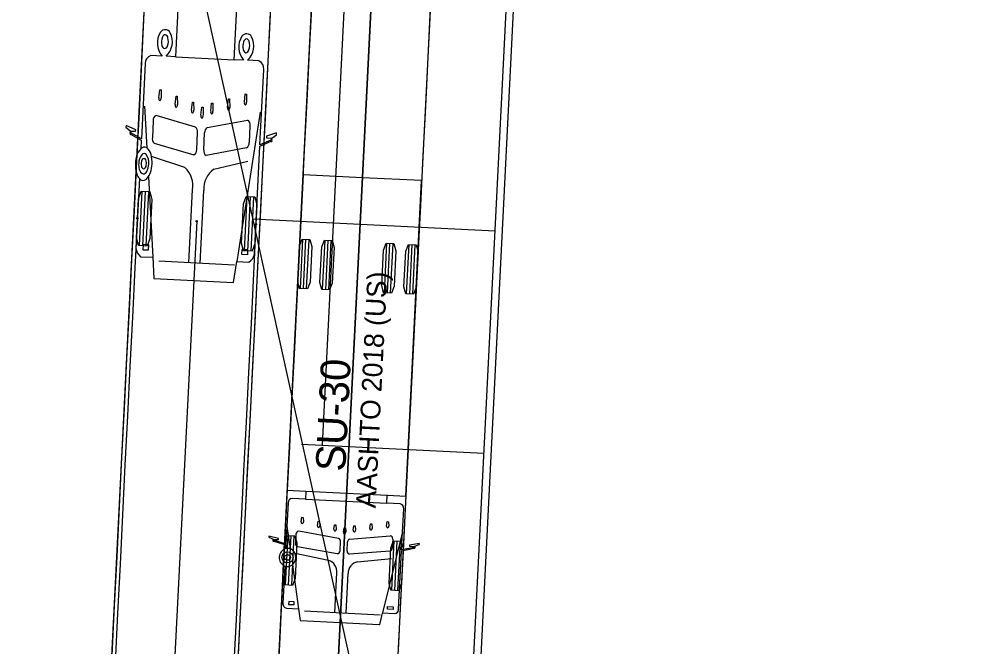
# Model space of a CAD drawing. Extents: x 260275 to 261282, y 610916 to 614143.
# Drawn here: x 261020 to 261084.3, y 612016.8 to 612059.1 of the extents above; entities that cross this region are included whole.
import ezdxf

# ---------------------------------------------------------------- set-up
doc = ezdxf.new("R2010")
doc.units = 0
for name, color, linetype in [('GE_X_Alignment', 7, 'Continuous'), ('PV_P_Curb', 7, 'Continuous'), ('PV_P_EOP', 7, 'Continuous'), ('PV_P_Joint', 7, 'Continuous'), ('UT_X_Water_Cells', 7, 'Continuous')]:
    doc.layers.add(name, color=color, linetype=linetype)

msp = doc.modelspace()

# ---------------------------------------------------------------- linework, layer by layer
at = {"layer": 'GE_X_Alignment'}
msp.add_line((260986.249, 610915.954), (261148.276, 614142.838), dxfattribs=at)
at = {"layer": 'PV_P_Curb'}
msp.add_line((261049.53, 611984.642), (261053.627, 612066.228), dxfattribs=at)
at = {"layer": 'PV_P_EOP'}
for p, q in [((261045.801, 612000.096), (261031.212, 612066.209)), ((261049.031, 611984.667), (261053.122, 612066.147))]:
    msp.add_line(p, q, dxfattribs=at)
at = {"layer": 'PV_P_Joint'}
for p, q in [((261040.428, 612030.404), (261042.684, 612075.347)), ((261035.717, 612045.659), (261052.052, 612044.839)), ((261039.021, 612030.475), (261051.3, 612029.858))]:
    msp.add_line(p, q, dxfattribs=at)
at = {"layer": 'UT_X_Water_Cells'}
for p, q in [((261044.031, 612066.726), (261023.69, 611661.632)), ((261029.631, 612056.616), (261028.857, 612056.655)), ((261030.518, 612056.572), (261034.487, 612056.372)), ((261036.148, 612056.289), (261035.373, 612056.328)), ((261029.404, 612053.801), (261029.468, 612054.348)), ((261029.468, 612054.348), (261029.55, 612054.344)), ((261029.55, 612054.344), (261029.559, 612053.793)), ((261030.501, 612053.36), (261030.564, 612053.907)), ((261030.564, 612053.907), (261030.647, 612053.903)), ((261030.647, 612053.903), (261030.655, 612053.352)), ((261034.027, 612053.158), (261034.091, 612053.73)), ((261034.091, 612053.73), (261034.173, 612053.726)), ((261034.173, 612053.726), (261034.181, 612053.15)), ((261035.162, 612053.512), (261035.226, 612054.059)), ((261035.226, 612054.059), (261035.308, 612054.055)), ((261035.308, 612054.055), (261035.317, 612053.504)), ((261028.435, 612053.233), (261028.587, 612050.433)), ((261031.6, 612052.97), (261031.663, 612053.517)), ((261031.663, 612053.517), (261031.746, 612053.513)), ((261031.746, 612053.513), (261031.754, 612052.962)), ((261032.232, 612052.629), (261032.295, 612053.176)), ((261032.295, 612053.176), (261032.378, 612053.172)), ((261032.378, 612053.172), (261032.386, 612052.622)), ((261032.895, 612052.905), (261032.958, 612053.452)), ((261032.958, 612053.452), (261033.041, 612053.448)), ((261033.041, 612053.448), (261033.049, 612052.897)), ((261031.879, 612051.833), (261029.221, 612052.612)), ((261032.657, 612051.794), (261035.38, 612052.303)), ((261036.225, 612052.842), (261034.653, 612042.773)), ((261029.021, 612052.251), (261028.964, 612051.122)), ((261035.543, 612051.924), (261035.487, 612050.794)), ((261027.489, 612051.551), (261027.47, 612051.569)), ((261027.515, 612051.551), (261027.489, 612051.551)), ((261031.955, 612050.326), (261032.012, 612051.455)), ((261032.43, 612050.302), (261032.487, 612051.432)), ((261036.971, 612051.076), (261036.997, 612051.074)), ((261036.997, 612051.074), (261037.018, 612051.089)), ((261029.097, 612050.744), (261031.755, 612049.966)), ((261035.317, 612050.432), (261032.593, 612049.923)), ((261031.149, 612049.103), (261028.908, 612049.852)), ((261033.11, 612049.004), (261035.403, 612049.523)), ((261028.694, 612048.471), (261028.99, 612043.058)), ((261028.09, 612048.368), (261027.854, 612043.673)), ((261028.092, 612043.844), (261028.276, 612047.506)), ((261028.321, 612043.832), (261028.505, 612047.494)), ((261028.55, 612043.821), (261028.734, 612047.483)), ((261031.428, 612042.71), (261031.673, 612047.595)), ((261032.192, 612042.671), (261032.438, 612047.557)), ((261035.167, 612043.489), (261035.351, 612047.151)), ((261035.396, 612043.477), (261035.58, 612047.139)), ((261035.625, 612043.466), (261035.809, 612047.128)), ((261031.95, 612045.486), (261010.925, 611626.741)), ((261038.94, 612040.955), (261039.108, 612044.284)), ((261039.148, 612040.945), (261039.316, 612044.274)), ((261039.357, 612040.934), (261039.524, 612044.264)), ((261040.439, 612040.88), (261040.606, 612044.209)), ((261040.647, 612040.87), (261040.814, 612044.199)), ((261040.855, 612040.859), (261041.022, 612044.188)), ((261044.6, 612040.671), (261044.767, 612044)), ((261044.808, 612040.661), (261044.975, 612043.99)), ((261045.016, 612040.65), (261045.183, 612043.979)), ((261028.343, 612043.927), (261028.325, 612043.571)), ((261028.325, 612043.571), (261028.704, 612043.552)), ((261028.721, 612043.908), (261028.343, 612043.927)), ((261028.704, 612043.552), (261028.721, 612043.908)), ((261034.987, 612043.237), (261035.005, 612043.592)), ((261035.005, 612043.592), (261035.383, 612043.573)), ((261035.383, 612043.573), (261035.366, 612043.218)), ((261046.098, 612040.596), (261046.265, 612043.925)), ((261046.306, 612040.585), (261046.473, 612043.915)), ((261046.514, 612040.575), (261046.681, 612043.904)), ((261029.394, 612042.812), (261034.492, 612042.556)), ((261035.366, 612043.218), (261034.987, 612043.237)), ((261029.068, 612041.626), (261034.432, 612041.356)), ((261039.302, 612027.3), (261044.787, 612027.025)), ((261039.275, 612026.769), (261044.76, 612026.494)), ((261038.984, 612025.242), (261039.035, 612025.54)), ((261039.035, 612025.54), (261039.118, 612025.536)), ((261039.118, 612025.536), (261039.138, 612025.234)), ((261038.028, 612024.954), (261038.245, 612023.42)), ((261040.09, 612024.976), (261040.14, 612025.274)), ((261040.14, 612025.274), (261040.223, 612025.269)), ((261040.223, 612025.269), (261040.244, 612024.968)), ((261041.196, 612024.738), (261041.247, 612025.035)), ((261041.247, 612025.035), (261041.33, 612025.031)), ((261041.33, 612025.031), (261041.35, 612024.73)), ((261041.835, 612024.537), (261041.886, 612024.835)), ((261041.886, 612024.835), (261041.969, 612024.831)), ((261041.969, 612024.831), (261041.989, 612024.529)), ((261042.491, 612024.673), (261042.542, 612024.97)), ((261042.542, 612024.97), (261042.624, 612024.966)), ((261042.624, 612024.966), (261042.645, 612024.665)), ((261043.616, 612024.785), (261043.667, 612025.096)), ((261043.667, 612025.096), (261043.749, 612025.092)), ((261043.749, 612025.092), (261043.77, 612024.777)), ((261044.742, 612024.953), (261044.793, 612025.251)), ((261044.793, 612025.251), (261044.876, 612025.246)), ((261044.876, 612025.246), (261044.897, 612024.945)), ((261037.937, 612020.98), (261038.105, 612024.31)), ((261038.146, 612020.97), (261038.313, 612024.299)), ((261038.354, 612020.96), (261038.521, 612024.289)), ((261038.636, 612024.404), (261038.605, 612023.788)), ((261041.501, 612024.11), (261038.828, 612024.596)), ((261042.279, 612024.071), (261044.988, 612024.287)), ((261045.819, 612024.562), (261044.478, 612019.095)), ((261045.159, 612024.076), (261045.128, 612023.46)), ((261038.747, 612023.578), (261041.42, 612023.092)), ((261041.612, 612023.285), (261041.642, 612023.901)), ((261042.086, 612023.261), (261042.117, 612023.877)), ((261045.095, 612020.621), (261045.262, 612023.95)), ((261045.303, 612020.611), (261045.47, 612023.94)), ((261045.511, 612020.6), (261045.678, 612023.929)), ((261040.834, 612022.634), (261038.579, 612023.095)), ((261044.966, 612023.266), (261042.258, 612023.05)), ((261042.795, 612022.536), (261045.073, 612022.767)), ((261037.893, 612022.254), (261037.766, 612019.735)), ((261038.396, 612022.345), (261038.815, 612019.379)), ((261041.258, 612019.134), (261041.392, 612021.798)), ((261042.023, 612019.095), (261042.156, 612021.76)), ((261038.149, 612019.869), (261038.139, 612019.675)), ((261038.139, 612019.675), (261038.518, 612019.656)), ((261038.527, 612019.85), (261038.149, 612019.869)), ((261038.518, 612019.656), (261038.527, 612019.85)), ((261044.801, 612019.341), (261044.811, 612019.535)), ((261044.811, 612019.535), (261045.189, 612019.516)), ((261039.224, 612019.236), (261044.322, 612018.98)), ((261045.18, 612019.322), (261044.801, 612019.341)), ((261045.189, 612019.516), (261045.18, 612019.322))]:
    msp.add_line(p, q, dxfattribs=at)
for points in [[(261009.34, 611680.102), (261030.965, 612110.617), (261039.455, 612110.191), (261039.447, 612110.045), (261039.447, 612110.045)], [(261039.447, 612110.045), (261018.12, 611685.301)], [(261020.965, 611687.133), (261041.34, 612092.893), (261049.33, 612092.492), (261049.322, 612092.345), (261049.322, 612092.345)], [(261049.322, 612092.345), (261028.546, 611678.469)], [(261041.039, 612086.901), (261040.872, 612083.572), (261040.705, 612080.244), (261040.537, 612076.915), (261040.37, 612073.586), (261040.203, 612070.258), (261040.036, 612066.929), (261039.869, 612063.601), (261039.702, 612060.272), (261039.535, 612056.943), (261039.367, 612053.615), (261039.2, 612050.286), (261039.033, 612046.958), (261038.866, 612043.629), (261038.699, 612040.3), (261038.532, 612036.972), (261038.365, 612033.643), (261038.198, 612030.314), (261038.03, 612026.986), (261037.863, 612023.657), (261037.696, 612020.329), (261037.529, 612017), (261037.362, 612013.671)], [(261049.029, 612086.5), (261048.862, 612083.171), (261048.694, 612079.843), (261048.527, 612076.514), (261048.36, 612073.185), (261048.193, 612069.857), (261048.026, 612066.528), (261047.859, 612063.199), (261047.692, 612059.871), (261047.525, 612056.542), (261047.357, 612053.214), (261047.19, 612049.885), (261047.023, 612046.556), (261046.856, 612043.228), (261046.689, 612039.899), (261046.522, 612036.57), (261046.355, 612033.242), (261046.187, 612029.913), (261046.02, 612026.585), (261045.853, 612023.256), (261045.686, 612019.927), (261045.519, 612016.599)], [(261035.116, 612056.341), (261034.487, 612056.372), (261035.018, 612066.959), (261031.049, 612067.158), (261030.518, 612056.572), (261029.888, 612056.603)], [(261040.036, 612066.926), (261039.869, 612063.598), (261039.702, 612060.269), (261039.534, 612056.94), (261039.367, 612053.612), (261039.2, 612050.283), (261039.033, 612046.954), (261038.866, 612043.626), (261038.699, 612040.297), (261038.532, 612036.969), (261038.364, 612033.64), (261038.197, 612030.311), (261038.03, 612026.983), (261037.863, 612023.654), (261037.696, 612020.325), (261037.529, 612016.997), (261037.362, 612013.668)], [(261048.026, 612066.525), (261047.859, 612063.196), (261047.692, 612059.868), (261047.524, 612056.539), (261047.357, 612053.21), (261047.19, 612049.882), (261047.023, 612046.553), (261046.856, 612043.225), (261046.689, 612039.896), (261046.522, 612036.567), (261046.354, 612033.239), (261046.187, 612029.91), (261046.02, 612026.582), (261045.853, 612023.253), (261045.686, 612019.924), (261045.519, 612016.596)], [(261037.056, 612062.424), (261036.889, 612059.095), (261036.722, 612055.767), (261036.555, 612052.438), (261036.388, 612049.109), (261036.221, 612045.781), (261036.054, 612042.452), (261035.886, 612039.124), (261035.719, 612035.795), (261035.552, 612032.466), (261035.385, 612029.138), (261035.218, 612025.809), (261035.051, 612022.48), (261034.884, 612019.152), (261034.716, 612015.823)], [(261028.4, 612059.522), (261028.233, 612056.193), (261028.066, 612052.864), (261027.898, 612049.536), (261027.731, 612046.207), (261027.564, 612042.878), (261027.397, 612039.55), (261027.23, 612036.221), (261027.063, 612032.892), (261026.896, 612029.564), (261026.729, 612026.235), (261026.561, 612022.907), (261026.394, 612019.578), (261026.227, 612016.249)], [(261028.479, 612056.116), (261028.224, 612051.04), (261027.521, 612051.432), (261027.521, 612051.432)], [(261036.954, 612050.958), (261036.953, 612050.958), (261036.214, 612050.639), (261036.469, 612055.714)], [(261027.511, 612051.469), (261027.515, 612051.551), (261027.836, 612051.551), (261027.841, 612051.654), (261027.193, 612051.944), (261027.187, 612051.824), (261027.47, 612051.569), (261027.466, 612051.482)], [(261027.5, 612051.346), (261028.219, 612050.941), (261028.191, 612050.368)], [(261037.013, 612051.002), (261037.018, 612051.089), (261037.325, 612051.315), (261037.331, 612051.435), (261036.657, 612051.211), (261036.652, 612051.108), (261036.971, 612051.076), (261036.967, 612050.995)], [(261035.844, 612043.272), (261036.209, 612050.54), (261036.966, 612050.871)], [(261045.658, 612026.449), (261044.763, 612026.494), (261044.76, 612026.498), (261044.787, 612027.024), (261044.798, 612027.024), (261046.039, 612026.962), (261047.107, 612048.222), (261043.112, 612048.422), (261039.117, 612048.623), (261038.049, 612027.363), (261039.291, 612027.301), (261039.302, 612027.299), (261039.275, 612026.773), (261039.272, 612026.769), (261038.377, 612026.814)], [(261027.956, 612045.686), (261027.788, 612042.358), (261027.621, 612039.029), (261027.454, 612035.7), (261027.287, 612032.372), (261027.12, 612029.043), (261026.953, 612025.714), (261026.786, 612022.386), (261026.618, 612019.057), (261026.451, 612015.729)], [(261035.945, 612045.285), (261035.778, 612041.957), (261035.611, 612038.628), (261035.444, 612035.299), (261035.277, 612031.971), (261035.11, 612028.642), (261034.943, 612025.313), (261034.775, 612021.985), (261034.608, 612018.656), (261034.441, 612015.327)], [(261028.176, 612043.099), (261028.99, 612043.058), (261029.067, 612041.638)], [(261029.068, 612041.626), (261034.432, 612041.356), (261034.653, 612042.773), (261035.467, 612042.733)], [(261038.107, 612026.512), (261037.968, 612023.741), (261037.962, 612023.73), (261037.157, 612023.99), (261037.157, 612023.99)], [(261046.589, 612023.516), (261046.589, 612023.516), (261045.762, 612023.338), (261045.758, 612023.35), (261045.897, 612026.121)], [(261037.147, 612024.011), (261037.148, 612024.055), (261037.149, 612024.055), (261037.466, 612024.048), (261037.469, 612024.048), (261037.471, 612024.104), (261037.468, 612024.105), (261036.82, 612024.277), (261036.818, 612024.277), (261036.814, 612024.212), (261037.102, 612024.066), (261037.102, 612024.066), (261037.101, 612024.018)], [(261037.137, 612023.943), (261037.138, 612023.943), (261037.958, 612023.676), (261037.964, 612023.663), (261037.952, 612023.436)], [(261045.557, 612019.344), (261045.754, 612023.272), (261045.761, 612023.284), (261046.603, 612023.468), (261046.604, 612023.468)], [(261046.648, 612023.539), (261046.651, 612023.586), (261046.651, 612023.587), (261046.952, 612023.703), (261046.956, 612023.768), (261046.953, 612023.768), (261046.291, 612023.662), (261046.288, 612023.661), (261046.285, 612023.605), (261046.287, 612023.605), (261046.604, 612023.581), (261046.604, 612023.58), (261046.602, 612023.536)], [(261038.004, 612019.42), (261038.811, 612019.379), (261038.815, 612019.375), (261038.925, 612018.597), (261038.967, 612018.592), (261041.607, 612018.46), (261044.248, 612018.327), (261044.29, 612018.327), (261044.477, 612019.09), (261044.482, 612019.095), (261045.288, 612019.054)]]:
    msp.add_lwpolyline(points, dxfattribs=at)
for points in [[(261028.607, 612043.818), (261028.036, 612043.847), (261027.889, 612044.368), (261028.022, 612047.005), (261028.22, 612047.509), (261028.791, 612047.48), (261028.937, 612046.959), (261028.805, 612044.322)], [(261035.681, 612043.463), (261035.11, 612043.492), (261034.964, 612044.013), (261035.096, 612046.65), (261035.294, 612047.154), (261035.865, 612047.125), (261036.012, 612046.604), (261035.879, 612043.967)], [(261039.408, 612040.932), (261038.889, 612040.958), (261038.756, 612041.432), (261038.876, 612043.829), (261039.056, 612044.287), (261039.575, 612044.261), (261039.708, 612043.787), (261039.588, 612041.39)], [(261040.906, 612040.857), (261040.387, 612040.883), (261040.254, 612041.357), (261040.374, 612043.754), (261040.554, 612044.212), (261041.073, 612044.186), (261041.206, 612043.712), (261041.086, 612041.315)], [(261045.068, 612040.648), (261044.548, 612040.674), (261044.415, 612041.148), (261044.536, 612043.545), (261044.716, 612044.003), (261045.235, 612043.977), (261045.368, 612043.503), (261045.248, 612041.106)], [(261046.566, 612040.572), (261046.046, 612040.598), (261045.913, 612041.072), (261046.034, 612043.469), (261046.214, 612043.928), (261046.733, 612043.902), (261046.866, 612043.428), (261046.746, 612041.031)], [(261038.405, 612020.957), (261037.886, 612020.983), (261037.753, 612021.457), (261037.873, 612023.854), (261038.053, 612024.312), (261038.572, 612024.286), (261038.705, 612023.812), (261038.585, 612021.415)], [(261045.563, 612020.598), (261045.043, 612020.624), (261044.91, 612021.098), (261045.031, 612023.495), (261045.211, 612023.953), (261045.73, 612023.927), (261045.863, 612023.453), (261045.743, 612021.056)]]:
    msp.add_lwpolyline(points, close=True, dxfattribs=at)
for centre, radius in [((261027.956, 612045.686), 0.0417), ((261031.95, 612045.486), 0.0417), ((261035.945, 612045.285), 0.0417), ((261038.068, 612022.838), 0.374), ((261038.068, 612022.838), 0.193)]:
    msp.add_circle(centre, radius, dxfattribs=at)
for centre, radius, start, end in [((261030.644, 612057.499), 1.344, 147.53526, 221.09006), ((261029.83, 612058.01), 0.383, 27.59628, 146.65472), ((261028.969, 612057.583), 1.344, 313.16094, 26.71574), ((261035.315, 612057.726), 0.387, 28.62104, 145.62996), ((261030.432, 612057.55), 0.86, 155.59014, 195.55953), ((261029.863, 612057.826), 0.228, 97.92836, 159.8232), ((261029.757, 612057.801), 0.262, 6.80834, 73.33353), ((261029.165, 612057.616), 0.879, 339.66236, 14.25761), ((261036.129, 612057.224), 1.344, 147.53526, 221.09006), ((261035.937, 612057.275), 0.879, 159.9934, 194.58864), ((261035.367, 612057.519), 0.262, 100.91747, 167.44267), ((261035.263, 612057.555), 0.228, 14.4278, 76.32264), ((261034.454, 612057.308), 1.344, 313.16094, 26.71574), ((261034.669, 612057.337), 0.86, 338.69148, 18.66086), ((261029.887, 612057.386), 0.29, 193.32121, 249.48124), ((261029.747, 612057.358), 0.247, 278.8428, 348.7219), ((261035.332, 612057.078), 0.247, 185.52911, 255.4082), ((261035.196, 612057.119), 0.29, 284.76976, 340.92979), ((261029.05, 612056.118), 0.571, 109.81853, 180.21012), ((261035.901, 612055.774), 0.571, 354.04089, 64.43248), ((261029.59, 612053.75), 0.192, 164.57524, 232.04981), ((261029.369, 612053.761), 0.192, 302.17384, 9.70311), ((261030.686, 612053.309), 0.192, 164.57524, 232.04981), ((261030.466, 612053.32), 0.192, 302.17384, 9.70311), ((261031.785, 612052.919), 0.192, 164.57524, 232.04981), ((261031.565, 612052.93), 0.192, 302.17384, 9.70311), ((261034.213, 612053.132), 0.192, 164.5479, 232.07716), ((261033.992, 612053.143), 0.192, 302.20119, 9.67576), ((261035.348, 612053.461), 0.192, 164.5479, 232.07716), ((261035.127, 612053.472), 0.192, 302.20119, 9.67576), ((261029.353, 612052.306), 0.334, 113.39037, 185.98833), ((261032.417, 612052.578), 0.192, 164.57524, 232.04981), ((261032.197, 612052.589), 0.192, 302.20119, 9.67576), ((261033.08, 612052.854), 0.192, 164.5479, 232.07716), ((261032.859, 612052.865), 0.192, 302.20119, 9.67576), ((261035.218, 612052.011), 0.334, 348.26267, 60.86063), ((261031.621, 612051.532), 0.397, 351.20134, 49.36435), ((261032.884, 612051.468), 0.397, 124.88665, 183.04966), ((261027.57, 612051.409), 0.127, 145.02093, 209.23008), ((261027.48, 612051.36), 0.0244, 212.94354, 326.25791), ((261027.411, 612051.424), 0.11, 4.06966, 24.17798), ((261029.361, 612051.049), 0.403, 169.66784, 229.12579), ((261028.425, 612050.18), 0.301, 57.35677, 141.25506), ((261028.098, 612049.802), 0.799, 12.92493, 52.19257), ((261035.084, 612050.762), 0.403, 305.12521, 4.58316), ((261037.062, 612050.94), 0.11, 150.07302, 170.18134), ((261036.987, 612050.882), 0.0244, 207.99309, 321.30746), ((261036.902, 612050.94), 0.127, 325.02093, 29.23008), ((261030.026, 612049.274), 2.204, 164.32456, 183.95974), ((261028.809, 612049.682), 0.924, 132.02262, 168.30076), ((261028.956, 612049.388), 0.913, 140.43513, 180.69541), ((261028.408, 612049.846), 0.199, 40.92879, 141.5681), ((261027.819, 612049.439), 0.914, 353.95993, 36.01791), ((261026.937, 612049.445), 2.012, 356.76687, 15.44978), ((261031.614, 612050.273), 0.342, 295.59721, 5.52369), ((261032.765, 612050.216), 0.342, 168.72731, 238.65379), ((261029.555, 612049.228), 1.731, 183.5106, 198.70836), ((261029.275, 612049.307), 1.234, 176.75519, 194.33734), ((261028.839, 612049.332), 0.631, 150.93378, 193.73431), ((261028.443, 612049.213), 0.22, 188.13535, 249.83363), ((261028.398, 612049.593), 0.12, 12.10162, 157.57965), ((261028.283, 612049.263), 0.27, 288.27444, 1.01824), ((261027.946, 612049.381), 0.617, 349.4131, 22.60389), ((261027.63, 612049.375), 1.098, 330.39127, 358.28386), ((261026.899, 612049.423), 2.049, 341.50654, 357.43184), ((261030.068, 612047.882), 1.631, 349.85894, 48.44967), ((261028.608, 612048.866), 0.719, 195.6559, 223.91288), ((261028.483, 612049.061), 0.407, 188.35614, 251.16055), ((261028.341, 612048.942), 0.268, 272.19814, 335.87577), ((261027.816, 612049.09), 1.074, 318.58211, 342.85096), ((261034.064, 612047.682), 1.631, 125.80134, 184.39207), ((261028.351, 612048.566), 0.328, 217.21385, 266.11819), ((261028.326, 612048.619), 0.38, 270.45588, 320.97941), ((261028.643, 612043.737), 0.792, 184.65895, 233.81442), ((261035.066, 612043.415), 0.792, 300.43659, 349.59206), ((261038.429, 612026.496), 0.323, 99.2771, 177.1255), ((261045.575, 612026.137), 0.323, 357.1255, 74.97391), ((261039.072, 612025.219), 0.091, 165.44206, 259.60593), ((261039.049, 612025.22), 0.0909, 274.60942, 8.84462), ((261040.178, 612024.953), 0.091, 165.44206, 259.60593), ((261040.154, 612024.954), 0.0909, 274.60942, 8.84462), ((261041.284, 612024.715), 0.091, 165.44206, 259.60593), ((261041.261, 612024.716), 0.0909, 274.60942, 8.84462), ((261042.579, 612024.65), 0.0909, 165.40639, 259.64159), ((261042.555, 612024.651), 0.091, 274.64508, 8.80895), ((261043.704, 612024.776), 0.0909, 165.40639, 259.64159), ((261043.68, 612024.777), 0.091, 274.64508, 8.80895), ((261044.83, 612024.93), 0.0909, 165.40639, 259.64159), ((261044.807, 612024.931), 0.091, 274.64508, 8.80895), ((261038.82, 612024.412), 0.184, 87.71808, 182.58934), ((261041.451, 612023.924), 0.193, 353.06366, 74.98801), ((261041.923, 612024.514), 0.091, 165.44206, 259.60593), ((261041.899, 612024.516), 0.091, 274.64508, 8.80895), ((261042.31, 612023.881), 0.193, 99.26299, 181.18734), ((261044.976, 612024.103), 0.184, 351.66167, 86.53293), ((261037.12, 612023.981), 0.0418, 117.61865, 294.63358), ((261037.114, 612023.982), 0.0434, 11.03902, 41.7118), ((261038.135, 612022.834), 0.628, 106.8788, 247.3705), ((261038.072, 612022.925), 0.524, 49.38452, 103.18459), ((261038.797, 612023.764), 0.193, 173.06859, 254.98308), ((261044.935, 612023.456), 0.193, 279.26792, 1.18241), ((261046.631, 612023.504), 0.0434, 132.53921, 163.21198), ((261046.625, 612023.504), 0.0418, 239.61742, 56.63235), ((261037.999, 612022.833), 0.629, 309.17109, 357.86038), ((261037.999, 612022.848), 0.63, 356.4803, 48.88311), ((261041.427, 612023.276), 0.184, 267.72364, 2.58377), ((261042.269, 612023.234), 0.184, 171.66723, 266.52737), ((261038.063, 612022.752), 0.526, 251.07067, 309.31667), ((261040.624, 612021.89), 0.773, 353.15088, 74.23504), ((261042.929, 612021.775), 0.773, 100.01597, 181.10013), ((261038.046, 612019.699), 0.282, 172.49767, 261.5771), ((261045.275, 612019.336), 0.282, 272.67391, 1.75333)]:
    msp.add_arc(centre, radius, start, end, dxfattribs=at)
for centre, major_axis, start_param, end_param in [((261027.482, 612051.413), (-0.0039, -0.0781), 2.398717, 3.668019), ((261027.482, 612051.413), (0.0039, 0.0781), 3.71124, 4.981984), ((261036.99, 612050.936), (0.0039, 0.0781), 5.756759, 7.026061), ((261036.99, 612050.936), (-0.0039, -0.0781), 4.442794, 5.713538)]:
    msp.add_ellipse(centre, major_axis=major_axis, ratio=0.5, start_param=start_param, end_param=end_param, dxfattribs=at)

# ---------------------------------------------------------------- texts
for s, height, p in [('AASHTO 2018 (US)', 1.33333, (261044.002, 612026.135)), ('SU-30', 2, (261041.956, 612028.598))]:
    msp.add_text(s, height=height, rotation=87.1255, dxfattribs=at).set_placement(p)

doc.saveas('drawing.dxf')
